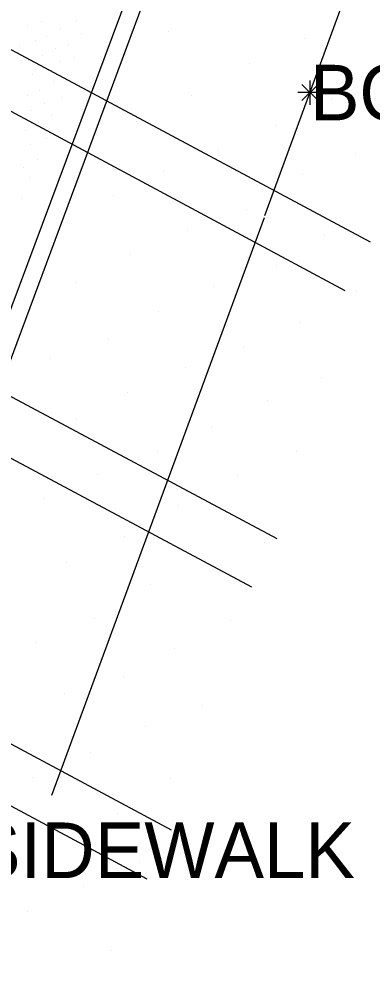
# Model space of a CAD drawing. Extents: x 1729983 to 1730242, y 468641 to 469019.
# Drawn here: x 1730082.18 to 1730093.62, y 468848.55 to 468879.25 of the extents above; entities that cross this region are included whole.
import ezdxf

# ---------------------------------------------------------------- set-up
doc = ezdxf.new("R2010")
doc.units = 0
for name, color, linetype in [('Default', 7, 'Continuous'), ('S_Curb_Type_1', 7, 'Continuous'), ('S_Ground_SpotElevation', 7, 'Continuous'), ('S_Misc_MiscFeature', 7, 'Continuous'), ('S_Misc_MiscItems', 7, 'Continuous'), ('S_Roadway_Edge_Pavement', 7, 'Continuous'), ('S_Text', 7, 'Continuous')]:
    doc.layers.add(name, color=color, linetype=linetype)

# ---------------------------------------------------------------- blocks, each defined once
blk = doc.blocks.new('POINT_DISPLAY')
at = {"layer": 'Default'}
blk.add_line((0, 0), (0, 0), dxfattribs=at)

msp = doc.modelspace()

# ---------------------------------------------------------------- linework, layer by layer
at = {"layer": 'S_Curb_Type_1'}
msp.add_lwpolyline([(1730127.344, 469003.745), (1730128.313, 469003.209), (1730129.005, 469001.957), (1730128.001, 468995.343), (1730121.966, 468978.7), (1730114.875, 468959.641), (1730107.952, 468940.794), (1730100.667, 468921.305), (1730089.464, 468890.124), (1730080.18, 468865.229), (1730072.814, 468845.368), (1730066.167, 468827.336), (1730059.271, 468808.011), (1730050.413, 468784.194), (1730032.961, 468736.85), (1730026.597, 468719.521), (1730017.926, 468696.116)], dxfattribs=at)
at = {"layer": 'S_Misc_MiscFeature'}
for p, q in [((1730093.566, 468872.011), (1730069.66, 468884.825)), ((1730092.753, 468870.437), (1730069.025, 468883.165)), ((1730090.141, 468872.874), (1730093.567, 468882.199)), ((1730090.546, 468862.393), (1730066.194, 468875.396)), ((1730089.729, 468860.828), (1730065.539, 468873.772)), ((1730083.251, 468854.083), (1730090.132, 468872.811)), ((1730087.126, 468852.958), (1730062.608, 468866.064)), ((1730086.334, 468851.361), (1730061.978, 468864.435))]:
    msp.add_line(p, q, dxfattribs=at)
at = {"layer": 'S_Misc_MiscItems'}
for p, q in [((1730091.607, 468877.255), (1730091.607, 468876.469)), ((1730091.869, 468876.6), (1730091.345, 468877.124)), ((1730091.869, 468877.124), (1730091.345, 468876.6)), ((1730092, 468876.862), (1730091.214, 468876.862))]:
    msp.add_line(p, q, dxfattribs=at)
at = {"layer": 'S_Roadway_Edge_Pavement'}
msp.add_lwpolyline([(1730128.624, 468995.344), (1730122.317, 468978.183), (1730114.717, 468957.613), (1730108.465, 468940.563), (1730101.987, 468923.258), (1730100.18, 468918.245), (1730089.85, 468889.621), (1730080.624, 468864.761), (1730073.33, 468845.31), (1730066.507, 468826.616), (1730059.612, 468807.458), (1730050.88, 468783.514), (1730042.113, 468759.912), (1730034.557, 468739.828), (1730031.891, 468732.687), (1730026.743, 468718.512), (1730018.434, 468695.905)], dxfattribs=at)

# ---------------------------------------------------------------- block references
at = {"layer": 'S_Ground_SpotElevation'}
for p in [(1730082.926, 468879.173), (1730084.038, 468879.186), (1730082.472, 468879.04), (1730083.521, 468878.927), (1730084.223, 468878.774), (1730087.017, 468878.832), (1730082.721, 468878.553), (1730083.069, 468878.688), (1730083.794, 468878.43), (1730091.427, 468878.631), (1730082.189, 468878.367), (1730083.36, 468878.295), (1730082.479, 468877.908), (1730082.94, 468878.065), (1730083.537, 468877.869), (1730083.982, 468878.006), (1730083.151, 468877.622), (1730089.66, 468877.793), (1730082.628, 468877.445), (1730083.298, 468877.224), (1730083.759, 468877.435), (1730082.842, 468876.921), (1730082.442, 468876.775), (1730083.554, 468876.704), (1730087.77, 468876.775), (1730092.319, 468876.64), (1730082.6, 468876.285), (1730083.016, 468876.517), (1730083.238, 468876.127), (1730082.815, 468875.89), (1730085.986, 468875.913), (1730090.491, 468875.803), (1730082.395, 468875.624), (1730083.058, 468875.375), (1730082.562, 468875.174), (1730088.638, 468874.978), (1730093.078, 468874.886), (1730082.334, 468874.446), (1730082.779, 468874.695), (1730086.857, 468874.306), (1730091.367, 468874.204), (1730082.525, 468874.105), (1730082.266, 468873.434), (1730085.245, 468873.51), (1730089.548, 468873.088), (1730087.657, 468872.393), (1730092.076, 468872.218), (1730085.791, 468871.599), (1730090.525, 468871.253), (1730084, 468870.7), (1730088.497, 468870.565), (1730093.123, 468870.423), (1730086.688, 468869.767), (1730091.277, 468869.417), (1730085.074, 468868.866), (1730089.443, 468868.594), (1730083.206, 468868.226), (1730087.576, 468867.957), (1730091.971, 468867.64), (1730085.701, 468867.133), (1730090.23, 468866.866), (1730084.045, 468866.257), (1730088.41, 468866.016), (1730091.16, 468865.235), (1730086.669, 468865.223), (1730084.71, 468864.487), (1730089.261, 468864.456), (1730082.983, 468863.702), (1730087.336, 468863.469), (1730085.586, 468862.488), (1730090.125, 468862.265), (1730083.733, 468861.627), (1730088.263, 468861.614), (1730086.44, 468860.913), (1730084.617, 468859.813), (1730089.021, 468859.749), (1730082.703, 468859.047), (1730087.225, 468858.828), (1730085.563, 468857.936), (1730083.647, 468857.397), (1730088.118, 468857.008), (1730086.285, 468856.324), (1730084.5, 468855.47), (1730082.606, 468854.651), (1730087.088, 468854.625), (1730085.358, 468853.503), (1730083.441, 468852.882), (1730086.09, 468851.896), (1730084.27, 468851.126), (1730082.444, 468850.303), (1730085.184, 468849.047)]:
    msp.add_blockref('POINT_DISPLAY', p, dxfattribs=at)

# ---------------------------------------------------------------- texts
at = {"layer": 'S_Text'}
for s, p in [('BOT CROSS BRACES', (1730091.607, 468875.962)), ('PAVED SIDEWALK', (1730071.796, 468851.402))]:
    msp.add_text(s, height=1.8, dxfattribs=at).set_placement(p)

doc.saveas('drawing.dxf')
